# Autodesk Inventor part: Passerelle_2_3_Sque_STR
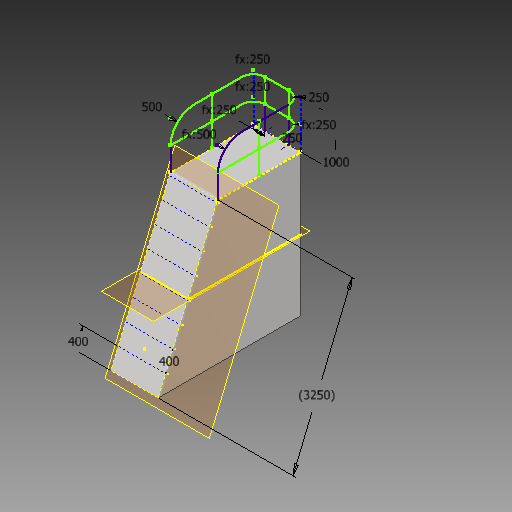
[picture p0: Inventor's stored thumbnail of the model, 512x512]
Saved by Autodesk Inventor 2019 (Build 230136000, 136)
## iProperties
Created: 2018-07
Part Number: Passerelle_2_3_Sque_STR
Material: Générique
Document SubType Name: Modeling
Designer: Fabian Perrée
Appearance: Par défaut
Surface Area: 252500 cm^2
Volume: 7.125e+06 cm^3
Author: Fabian Perrée
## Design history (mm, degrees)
sketch "Esquisse1"
  geometry: L1 (-500, 0)-(500, 0); L2 (500, 0)-(500, 3000); L3 (500, 3000)-(-500, 3000); L4 (-500, 3000)-(-500, 0); 2 further points
  constraints: 8 end point, 2 parallel, 1 coincident, 1 horizontal, 1 midpoint, 1 perpendicular
  dimensions: "d0" = 3000 distance of L3.end L1.start; "d1" = 1000 distance of L2.end L3.end
extrude "Extrusion1" new body sketch "Esquisse1" stored distance "d2" = 3000; taper "d3" = 0 deg
sketch "Esquisse2"
  geometry: L1 (3000, 3000)-(0, 3000) reference; L2 (3000, 0)-(0, 0) reference; L3 (3000, 3000)-(1250, 3000); L4 (1250, 3000)-(0, 0); L5 (1250, 3000)-(0, 3000); L6 (0, 3000)-(0, 0); 1 further point
  constraints: 8 end point, 1 collinear, 1 perpendicular, 1 point on line
  dimensions: "d4" = 1750 distance of L1.start L3.end
extrude "Extrusion2" cut sketch "Esquisse2" extent not by distance; stored distance "d5" = 3000; taper "d6" = 0 deg
sketch "Esquisse3" dims "d14" = 10
  geometry: L1 (0, 0)-(0, 3250) reference; L2 (0, 0)-(1000, 0) reference; L3 (1000, 3250)-(1000, 0) reference; L4 (0, 3250)-(1000, 3250) reference; L5 (1000, 1153.846)-(1000, 0) reference; L6 (1000, 400)-(0, 400); L7 (0, 0)-(0, 1153.846) reference; L8 (1000, 800)-(0, 800); L9 (1000, 1200)-(0, 1200); L10 (1000, 1600)-(0, 1600); L11 (1000, 2000)-(0, 2000); L12 (1000, 2400)-(0, 2400); L13 (1000, 2800)-(0, 2800); L14 (1000, 3200)-(0, 3200); 1 further point
  constraints: 16 end point, 2 point on line, 1 perpendicular, 1 vertical, 21 other
  dimensions: "d7" = 400 distance between parallel lines of L2 L6; "d8" = 3250 distance of L3.start L2.end (derived); "d11" = 400 distance of L6.start L8.start
node "Plan de construction1"
sketch "Esquisse4"
  geometry: L1 (1000, 400)-(0, 400) reference; L2 (1000, 800)-(0, 800) reference; L3 (1000, 1200)-(0, 1200) reference; L4 (1000, 1600)-(0, 1600) reference; L5 (1000, 2000)-(0, 2000) reference; L6 (1000, 2400)-(0, 2400) reference; L7 (1000, 2800)-(0, 2800) reference; L8 (1000, 3200)-(0, 3200) reference; 1 further point
node "Plan de construction2"
sketch "Esquisse5"
  geometry: L1 (1000, -2375)-(0, -2375) reference; L2 (0, -2375)-(0, 0) reference; L3 (0, 0)-(1000, 0) reference; L4 (1000, 0)-(1000, -2375) reference; 1 further point
  node "Projeter les arêtes coupées1"
sketch "Esquisse 3D1" dims "d17" = 1000, "d18" = 500, "d19" = 500 (= d18), "d20" = 250, "d21" = 250 (= d20), "d22" = 250 (= d20), "d23" = 250 (= d20), "d26" = 250, "d27" = 250 (= d26)
node "Solide1"
